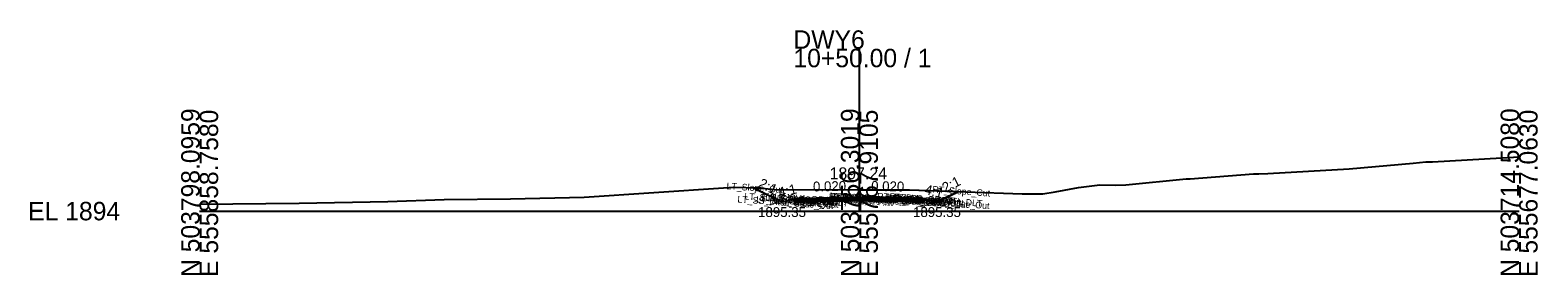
# Model space of a CAD drawing. Extents: x -26 to 1503, y -10 to 1030.
# Drawn here: x -25.7 to 202.8, y 490.3 to 527.5 of the extents above; entities that cross this region are included whole.
import ezdxf

# ---------------------------------------------------------------- set-up
doc = ezdxf.new("R2010")
doc.units = 0
for name, color, linetype in [('Default', 7, 'Continuous'), ('Exist Cross Section Cell', 7, 'Continuous'), ('Exist XS Center Line Elevation Label', 7, 'Continuous'), ('Exist XS Ground Line', 7, 'Continuous'), ('Prop CMT Pvmt Course 1', 7, 'Continuous'), ('Prop CMT Pvmt Course 2', 7, 'Continuous'), ('Prop CMT Pvmt Surface', 7, 'Continuous'), ('Prop CMT Shld Paved Course 1', 7, 'Continuous'), ('Prop CMT Shld Paved Course 2', 7, 'Continuous'), ('Prop CMT Slope Grass', 7, 'Continuous'), ('Prop CMT Subgrade Earthwork', 7, 'Continuous'), ('Prop XS Ditch Standard Text', 7, 'Continuous'), ('Prop XS Earthwork Shape', 7, 'Continuous'), ('Prop XS SE Text', 7, 'Continuous'), ('Prop XS Side Slope Text', 7, 'Continuous'), ('Typical Text Centerline CELL', 7, 'Continuous')]:
    doc.layers.add(name, color=color, linetype=linetype)

msp = doc.modelspace()

# ---------------------------------------------------------------- linework, layer by layer
at = {"layer": 'Exist Cross Section Cell'}
for p, q in [((100, 500), (100, 524.65)), ((0, 500), (100, 500)), ((100, 500), (200, 500))]:
    msp.add_line(p, q, dxfattribs=at)
at = {"layer": 'Exist XS Ground Line'}
for p, q in [((183.95, 507.27), (185.88, 507.46)), ((185.88, 507.46), (186.86, 507.5)), ((186.86, 507.5), (200, 508.22)), ((150.16, 504.92), (159.74, 505.65)), ((159.74, 505.65), (160.54, 505.67)), ((160.54, 505.67), (161.89, 505.72)), ((161.89, 505.72), (174.26, 506.4)), ((174.26, 506.4), (183.95, 507.27)), ((58.26, 502.1), (79.4, 503.51)), ((79.4, 503.51), (80.94, 503.63)), ((80.94, 503.63), (84.71, 503.51)), ((84.71, 503.51), (87.2, 503.3)), ((87.2, 503.3), (100, 503.24)), ((100, 503.24), (103.07, 503.22)), ((103.07, 503.22), (107.61, 503.23)), ((107.61, 503.23), (124.66, 502.64)), ((127.81, 502.6), (129.66, 502.93)), ((129.66, 502.93), (133.21, 503.58)), ((133.21, 503.58), (136.47, 503.99)), ((136.47, 503.99), (138.89, 503.93)), ((138.89, 503.93), (140.38, 503.99)), ((140.38, 503.99), (149.55, 504.88)), ((149.55, 504.88), (150.16, 504.92)), ((0, 501.07), (15.07, 501.21)), ((15.07, 501.21), (28.53, 501.46)), ((28.53, 501.46), (37.08, 501.78)), ((37.08, 501.78), (47.12, 501.87)), ((47.12, 501.87), (58.26, 502.1)), ((124.66, 502.64), (127.81, 502.6))]:
    msp.add_line(p, q, dxfattribs=at)
at = {"layer": 'Prop CMT Pvmt Course 1'}
for points in [[(100, 502.11), (91.25, 501.93)], [(91.25, 501.93), (91.25, 501.68)], [(91.25, 501.68), (100, 501.86)], [(100, 501.86), (100, 502.11)], [(100, 502.11), (108.75, 501.93)], [(100, 501.86), (100, 502.11)], [(108.75, 501.68), (100, 501.86)], [(108.75, 501.93), (108.75, 501.68)]]:
    msp.add_lwpolyline(points, dxfattribs=at)
msp.add_lwpolyline([(100, 501.86), (100, 501.98), (100, 501.98), (100, 501.86)], close=True, dxfattribs=at)
msp.add_lwpolyline([(100, 501.86), (100, 501.98), (100, 501.98), (100, 501.86)], close=True, dxfattribs=at)
at = {"layer": 'Prop CMT Pvmt Course 2'}
for points in [[(100, 501.86), (91.25, 501.68)], [(91.25, 501.68), (91.25, 501.43)], [(91.25, 501.43), (100, 501.61)], [(100, 501.61), (100, 501.86)], [(100, 501.61), (100, 501.86)], [(100, 501.86), (108.75, 501.68)], [(108.75, 501.43), (100, 501.61)], [(108.75, 501.68), (108.75, 501.43)]]:
    msp.add_lwpolyline(points, dxfattribs=at)
at = {"layer": 'Prop CMT Pvmt Surface'}
for points in [[(100, 502.11), (91.25, 501.93)], [(100, 502.11), (108.75, 501.93)]]:
    msp.add_lwpolyline(points, dxfattribs=at)
at = {"layer": 'Prop CMT Shld Paved Course 1'}
for points in [[(91.25, 501.93), (91, 501.68)], [(91, 501.68), (91.25, 501.68)], [(91.25, 501.68), (91.25, 501.93)], [(108.75, 501.93), (109, 501.68)], [(108.75, 501.68), (108.75, 501.93)], [(109, 501.68), (108.75, 501.68)]]:
    msp.add_lwpolyline(points, dxfattribs=at)
at = {"layer": 'Prop CMT Shld Paved Course 2'}
for points in [[(91.25, 501.68), (91, 501.68), (90.5, 501.67), (90.25, 501.42)], [(90.25, 501.42), (91.25, 501.43)], [(91.25, 501.43), (91.25, 501.68)], [(108.75, 501.68), (109, 501.68), (109.5, 501.67), (109.75, 501.42)], [(108.75, 501.43), (108.75, 501.68)], [(109.75, 501.42), (108.75, 501.43)]]:
    msp.add_lwpolyline(points, dxfattribs=at)
at = {"layer": 'Prop CMT Slope Grass'}
for points in [[(91.25, 501.93), (90.25, 501.85), (88.25, 501.35), (83.86, 503.55)], [(108.75, 501.93), (109.75, 501.85), (111.75, 501.35), (115, 502.98)]]:
    msp.add_lwpolyline(points, dxfattribs=at)
at = {"layer": 'Prop CMT Subgrade Earthwork'}
for points in [[(91.25, 501.43), (90.25, 501.42), (89.91, 501.77)], [(100, 501.61), (91.25, 501.43)], [(100, 501.61), (108.75, 501.43)], [(108.75, 501.43), (109.75, 501.42), (110.09, 501.77)]]:
    msp.add_lwpolyline(points, dxfattribs=at)
at = {"layer": 'Prop XS Earthwork Shape'}
for points in [[(107.61, 503.23), (115, 502.98), (111.75, 501.35), (110.09, 501.77), (109.75, 501.85), (108.75, 501.93), (100, 502.11), (91.25, 501.93), (90.25, 501.85), (89.91, 501.77), (88.25, 501.35), (83.88, 503.54), (84.71, 503.51), (87.2, 503.3), (100, 503.24), (103.07, 503.22)], [(100, 502.11), (108.75, 501.93), (109.75, 501.85), (110.09, 501.77), (109.75, 501.42), (108.75, 501.43), (100, 501.61), (91.25, 501.43), (90.25, 501.42), (89.91, 501.77), (90.25, 501.85), (91.25, 501.93)]]:
    msp.add_lwpolyline(points, close=True, dxfattribs=at)

# ---------------------------------------------------------------- texts
at = {"layer": 'Default'}
msp.add_text('-', height=0.0001, dxfattribs=at).set_placement((0, 500))
at = {"layer": 'Exist Cross Section Cell'}
for s, p in [('DWY6', (90, 524.65)), ('10+50.00 / 1', (90, 521.85)), ('EL 1894', (-26, 498.6))]:
    msp.add_text(s, height=2.8, dxfattribs=at).set_placement(p)
for s, p in [('N 503798.0959', (0, 490)), ('E 555858.7580', (2.8, 490)), ('N 503756.3019', (100, 490)), ('E 555767.9105', (102.8, 490)), ('N 503714.5080', (200, 490)), ('E 555677.0630', (202.8, 490))]:
    msp.add_text(s, height=2.8, rotation=90, dxfattribs=at).set_placement(p)
at = {"layer": 'Exist XS Center Line Elevation Label'}
msp.add_text('1897.24', height=1.8, dxfattribs=at).set_placement((95.49, 504.83))
at = {"layer": 'Prop XS Ditch Standard Text'}
for p in [(84.65, 499.1), (108.14, 499.1)]:
    msp.add_text('1895.35', height=1.5, dxfattribs=at).set_placement(p)
at = {"layer": 'Prop XS SE Text'}
for rotation, p in [(1.1458, (92.98, 502.97)), (358.8542, (101.77, 503.07))]:
    msp.add_text('0.020', height=1.5, rotation=rotation, dxfattribs=at).set_placement(p)
at = {"layer": 'Prop XS Side Slope Text'}
for s, rotation, p in [('2:1', 26.5651, (113.01, 502.78)), ('2:1', 333.4349, (84.57, 503.72)), ('4:1', 14.0362, (87.92, 502.04)), ('4:1', 345.9638, (109.77, 502.62))]:
    msp.add_text(s, height=1.5, rotation=rotation, dxfattribs=at).set_placement(p)
at = {"layer": 'Typical Text Centerline CELL'}
for s, p in [('LT_Slope_Cut', (79.84, 503.33)), ('RT_PV1_OEEOP', (95.43, 501.8)), ('LT_PV1_OEEOP', (95.49, 501.8)), ('PV1_PGL', (97.44, 501.78)), ('RT_Sub_Trench_Out_DLT', (102.66, 501.78)), ('RT_Slope_Cut', (111.04, 502.82)), ('LT_SS_Ditch_Base_Out', (81.49, 501.32)), ('LT_Sub_Trench_Out_DLT', (82.54, 501.78)), ('LT_Sub_Trench_Out', (84.34, 501.33)), ('LT_PS2_Shelf_Out', (85.13, 501.54)), ('LT_GS_OS_CTL', (85.69, 501.67)), ('LT_PS2_OEOP', (86.76, 501.47)), ('LT_PV2_OEOT', (86.97, 501.48)), ('LT_Sub_OEOT', (87, 501.23)), ('LT_PV1_OEOT', (87.09, 501.72)), ('RT_PV2_OEEOP', (95.31, 501.68)), ('RT_Sub_OEEOP', (95.33, 501.43)), ('LT_PV2_OEEOP', (95.37, 501.68)), ('LT_Sub_OEEOP', (95.39, 501.43)), ('RT_PV2_IEEOP', (95.69, 501.66)), ('LT_PV2_IEEOP', (95.75, 501.65)), ('RT_PV1_IEEOP', (95.81, 501.77)), ('LT_PV1_IEEOP', (95.87, 501.77)), ('PV2_PGL', (97.32, 501.54)), ('RT_Sub_Trench_Out', (103.78, 501.34)), ('RT_PS2_Shelf_Out', (104.08, 501.54)), ('RT_PV2_OEOT', (104.41, 501.48)), ('RT_Sub_OEOT', (104.43, 501.23)), ('RT_PV1_OEOT', (104.53, 501.73)), ('RT_PS2_OEOP', (104.7, 501.48)), ('RT_SS_Ditch_Base_Out', (104.93, 501.33)), ('RT_GS_OS_CTL', (105.13, 501.67))]:
    msp.add_text(s, height=1, rotation=356, dxfattribs=at).set_placement(p)

doc.saveas('drawing.dxf')
